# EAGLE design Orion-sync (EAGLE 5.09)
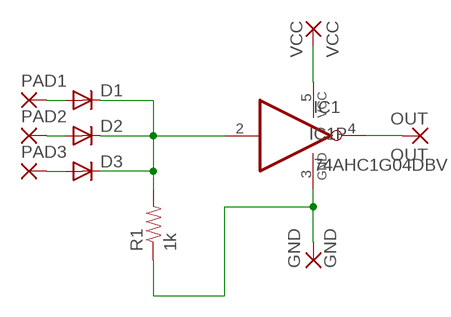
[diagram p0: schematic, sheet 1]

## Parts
D1  DIODESMA  [SMA-DIODE]
D2  DIODESMA  [SMA-DIODE]
D3  DIODESMA  [SMA-DIODE]
GND  GND  SMD5  [SMD2,54-5,08]
IC1  74AHC1G04DBV  [SOT23-5]
OUT  OUT  SMD5  [SMD2,54-5,08]
PAD1  SMD5  [SMD2,54-5,08]
PAD2  SMD5  [SMD2,54-5,08]
PAD3  SMD5  [SMD2,54-5,08]
R1  1k  RESISTOR1206  [1206]
VCC  VCC  SMD5  [SMD2,54-5,08]

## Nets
N$1: GND.1(P) IC1.3(GND) R1.1
N$2: IC1.5(VCC) VCC.1(P)
N$3: D1.A PAD1.1(P)
N$4: D2.A PAD2.1(P)
N$5: D3.A PAD3.1(P)
N$6: D1.C D2.C IC1.2(I) R1.2
N$7: IC1.4(O) OUT.1(P)
N$8: D3.C

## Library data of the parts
D1-D3 = SparkFun:DIODE: Diode
GND OUT PAD1-PAD3 VCC = wirepad:SMD5: SMD PAD
IC1 = 74xx-little-us:74*1G04: INVERTER Gate
R1 = SparkFun:RESISTOR: Resistor

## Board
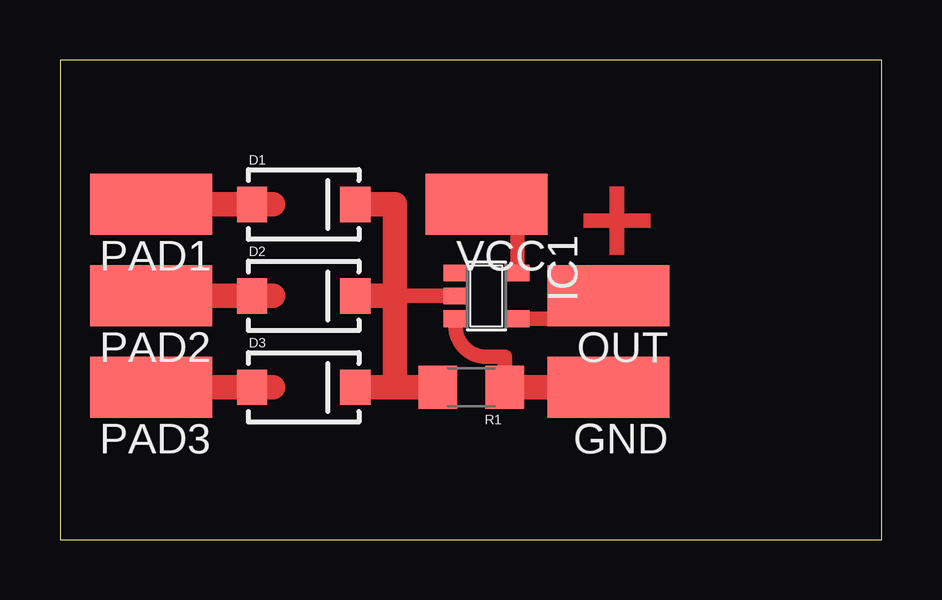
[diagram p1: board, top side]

Size 34.27 x 19.99 mm. Coordinates in mm from the lower left corner, seen from the top.
Outline: 0,0 34.27,0 34.27,19.99 0,19.99 0,0
Copper layers (1*16): Top 0.035mm / dielectric 1.5mm / Bottom 0.035mm
Design rules "default": minimum track width 10mil, minimum drill 24mil, track to track 8mil, track to pad 8mil, pad to pad 8mil, via to via 8mil, smd to smd 8mil, copper to edge 40mil, drill to drill 8mil, minimum pad ring 10mil, minimum via ring 8mil, stop-mask expansion 4mil, vias tented up to drill 0mil, thermal gap 10mil

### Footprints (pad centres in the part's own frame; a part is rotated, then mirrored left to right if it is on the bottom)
SMA-DIODE = smd 1.27 x 1.47: A -2.15,0; C 2.15,0
SMD2,54-5,08 = smd 2.54 x 5.08: 1 0,0
SOT23-5 = smd 0.69 x 0.99: 1 -0.95,-1.29; 2 0,-1.29; 3 0.95,-1.29; 4 0.95,1.3; 5 -0.95,1.3
1206 = smd 1.6 x 1.8: 1 -1.4,0; 2 1.4,0

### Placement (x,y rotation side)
D1  10.16,13.97 0 top
D2  10.16,10.16 0 top
D3  10.16,6.35 0 top
GND  22.86,6.35 90 top
IC1  17.78,10.16 270 top
OUT  22.86,10.16 90 top
PAD1  3.81,13.97 90 top
PAD2  3.81,10.16 90 top
PAD3  3.81,6.35 90 top
R1  17.14,6.35 180 top
VCC  17.78,13.97 90 top

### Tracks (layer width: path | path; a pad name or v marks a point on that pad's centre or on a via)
N$1
  Top 0.61: R1.1 18.55,7.62 17.78,7.62 arc-90 16.49,8.91 IC1.3
  Top 1.016: R1.1 GND.1
N$2
  Top 0.61: IC1.5 19.08,13.97 VCC.1
N$3
  Top 1.016: PAD1.1 D1.A 8.89,13.97
N$4
  Top 1.016: PAD2.1 7.62,10.16 D2.A 8.89,10.16
N$5
  Top 1.016: PAD3.1 7.62,6.35 D3.A 8.89,6.35
N$6
  Top 0.61: 13.97,10.16 IC1.2
  Top 1.016: D1.C 13.97,13.97 13.97,10.16 | D2.C 13.97,10.16 | 13.97,10.16 13.97,6.35 | 13.97,6.35 12.7,6.35 | 13.97,6.35 R1.2
N$7
  Top 0.61: IC1.4 23.18,9.21 arc90 24.13,10.16 OUT.1

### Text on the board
Top: +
